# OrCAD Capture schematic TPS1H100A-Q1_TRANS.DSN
size D; title: TPS1H100A-Q1:40-V, 100-mOhm Single-Channel Smart; rev: 1.0; note: Datasheet: SLVSCM2D     EVM: SLVUAB4; note: High-Side Power Switch
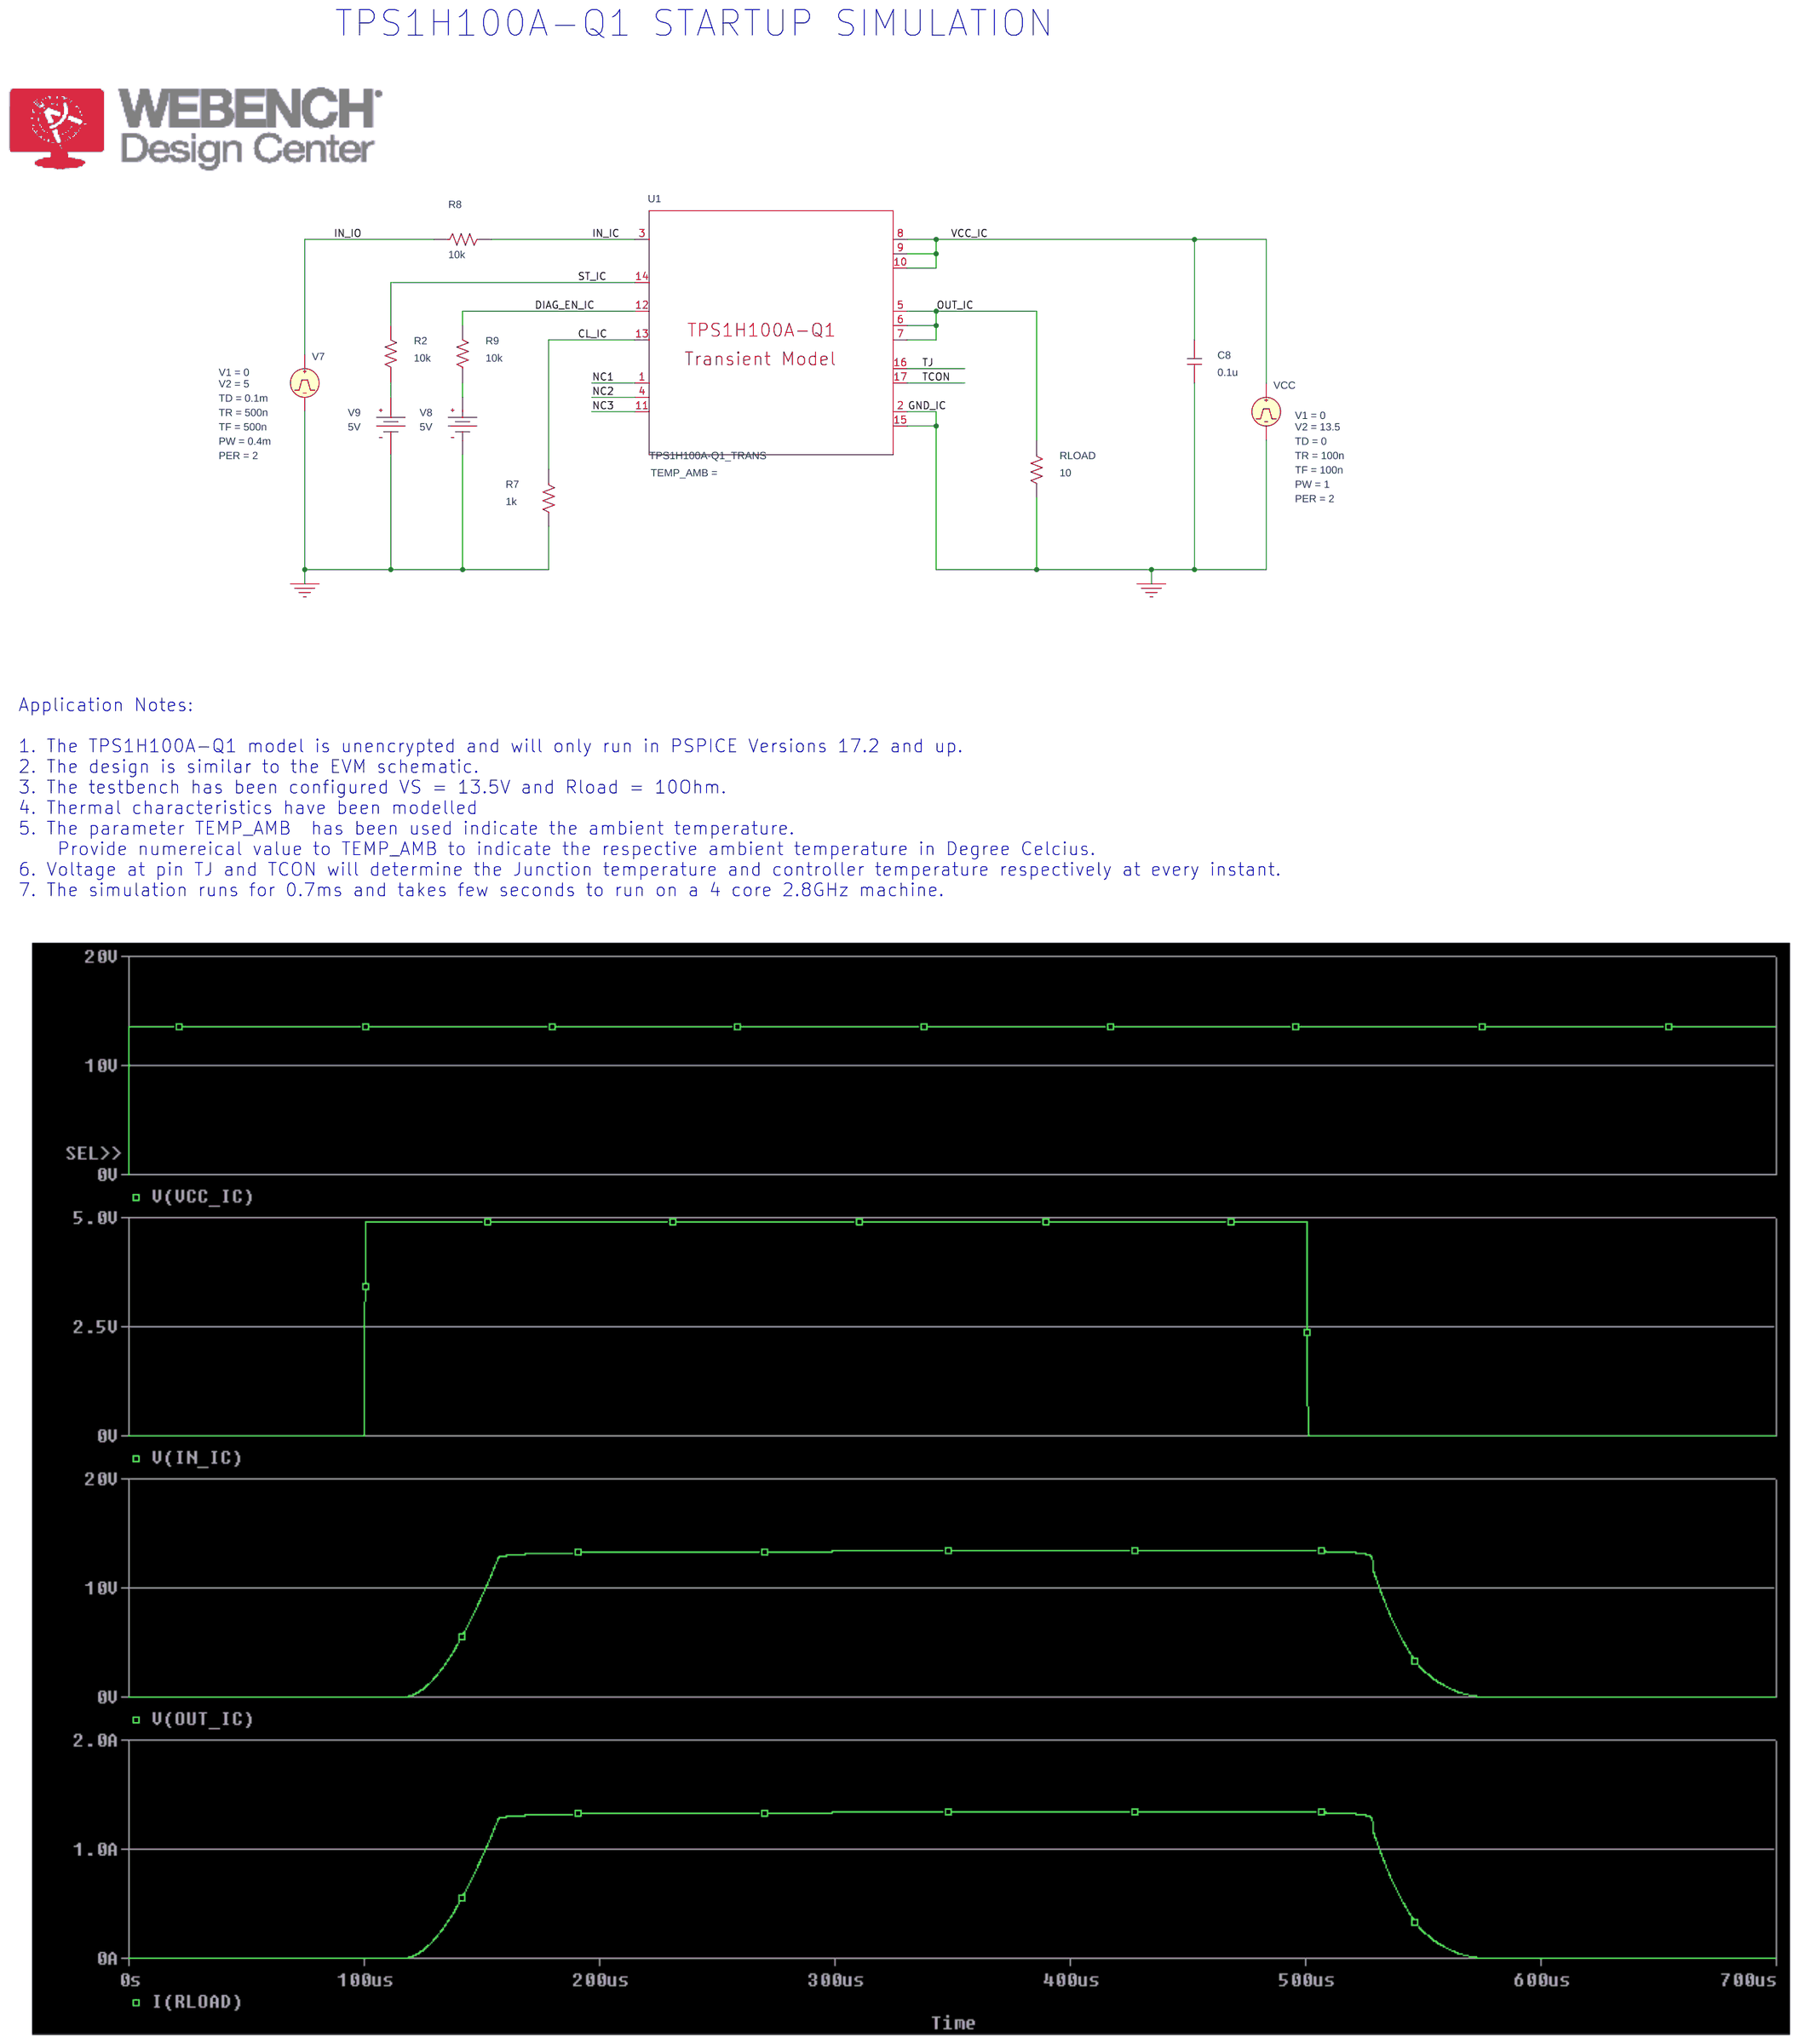
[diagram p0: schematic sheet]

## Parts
C8  0.1u  [RAD/CK05]
R2  10k  [AX/RC05]
R7  1k  [AX/RC05]
R8  10k  [AX/RC05]
R9  10k  [AX/RC05]
RLOAD  10  [AX/RC05]
U1  TPS1H100A-Q1_TRANS
V7  VPULSE
V8  VDC
V9  VDC
VCC  VPULSE

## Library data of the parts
C8 = C
R2 R7-R9 RLOAD = R
U1 = TPS1H100A-Q1_TRANS
V7 = VPULSE: PER: 2; PW: 0.4m; TD: 0.1m; TF: 500n; TR: 500n; V1: 0; V2: 5
V8 V9 = VDC: DC: 5V
VCC = VPULSE: PER: 2; PW: 1; TD: 0; TF: 100n; TR: 100n; V1: 0; V2: 13.5

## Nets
VCC_IC: C8.2 U1.8(VS_0) U1.9(VS_1) U1.10(VS_2) VCC.1(+)
0: C8.1 R7.2 RLOAD.2 U1.2(GND) U1.15(PAD) V7.2(-) V8.1(-) V9.1(-) VCC.2(-)
CL_IC: R7.1 U1.13(CL)
DIAG_EN_IC: R9.2 U1.12(DIAG_EN)
IN_IC: R8.2 U1.3(IN)
IN_IO: R8.1 V7.1(+)
NC1: U1.1(NC_0)
NC2: U1.4(NC_1)
NC3: U1.11(NC_2)
OUT_IC: RLOAD.1 U1.5(OUT_0) U1.6(OUT_1) U1.7(OUT_2)
ST_IC: R2.2 U1.14(STB)
TCON: U1.17(TCON)
TJ: U1.16(TJ)
N00819: R2.1 V9.0(+)
N16779099: R9.1 V8.0(+)

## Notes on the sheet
- TPS1H100A-Q1 STARTUP SIMULATION
- Application Notes:
  1. The TPS1H100A-Q1 model is unencrypted and will only run in PSPICE Versions 17.2 and up.
  2. The design is similar to the EVM schematic.
  3. The testbench has been configured VS = 13.5V and Rload = 10Ohm.
  4. Thermal characteristics have been modelled
  5. The parameter TEMP_AMB  has been used indicate the ambient temperature.
      Provide numereical value to TEMP_AMB to indicate the respective ambient temperature in Degree Celcius.
  6. Voltage at pin TJ and TCON will determine the Junction temperature and controller temperature respectively at every instant.
  7. The simulation runs for 0.7ms and takes few seconds to run on a 4 core 2.8GHz machine.
